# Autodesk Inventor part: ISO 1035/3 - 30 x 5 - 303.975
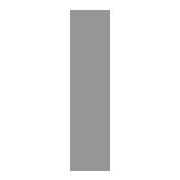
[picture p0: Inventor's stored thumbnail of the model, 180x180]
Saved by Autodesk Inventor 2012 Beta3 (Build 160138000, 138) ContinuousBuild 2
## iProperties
_CCFamilyMember: 18
_CCFamilyDisplayName: ISO 1035/3 - 1980 - Hot-rolled steel bars - Part 3: flat bars
_FrameMemberDoc: Frame Member File
_Version: 15.0.0
_GetPNFromCC: 1
Created: 2010-11
Part Number: ISO 1035/3 - 30 x 5 - 303.975
Material: Steel, Mild
Description: Hot-rolled steel bars - Part 3: flat bars
Document SubType Name: Modeling
Standard: ISO
Designer: Beta-8540w
Standard Revision: First edition 1980-11-01
Standards Organization: ISO
Language: en-US
Size Designation: 30x 5
Categories: <MemberInstance><Categories><Category DisplayName="Structural Shapes" InternalName="089c4875-fa83-4c05-b084-43b9cc11f5ed" Mnemonic="GRDR"><CategoryParameter Dis
Stock Number: 30x 5
Density: 7.86 g/cm^3
IsCustomPart: 1
G_L: 303.975 mm
G_W: 5.000 mm
G_H: 30.000 mm
Author: Beta-8540w
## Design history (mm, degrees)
node "Start plane"
node "End plane"
node "Driven Length"
  sketch "Sketch3"
    geometry: L1 (0, 0)-(10, 0) reference
    constraints: 2 end point, 1 horizontal
  workplane "Work Plane3"
  sketch "Sketch4"
    geometry: L1 (-2, 0)-(12, 0) reference; L2 (-2, 303.975)-(12, 303.975) reference
    dimensions: "d9" = 303.9749 distance between parallel lines of L1 L2 (derived)
sketch "Sweep Path"
  geometry: L1 through (40, 30) direction (1, 0); L2 through (-20, 135) direction (1, -0); L3 through (-20, 165) direction (1, 0); L4 through (40, 270) direction (1, 0); 14 other entities
  constraints: 20 horizontal
node "Orientation Work Plane"
feature "Body" dims "d10" = 0
body "Solid1"
sketch "Sketch"
  geometry: L1 (2.5, -15)-(-2.5, -15); L2 (-2.5, -15)-(-2.5, 15); L3 (-2.5, 15)-(2.5, 15); L4 (2.5, 15)-(2.5, -15); L5 (-6, 0)-(8, 0); L6 (0, -30)-(0, 40); L7 (0, 54)-(0, -44); L8 (-9.2, 0)-(13.2, 0)
  constraints: 16 end point, 2 collinear, 2 parallel, 1 horizontal, 1 perpendicular
  dimensions: "d0" = 30 distance between parallel lines of L3 L1 (= G_W); "d1" = 5 distance between parallel lines of L4 L2 (= G_H); "d4" = 2.5 distance between parallel lines of L6 L4 (= 0.5 x d1); "d5" = 15 distance between parallel lines of L5 L3 (= 0.5 x d0)
other parameters: "G_W" = 30 [user parameter; used in 1 equation term], "G_H" = 5 [user parameter; used in 1 equation term], "G_L" = 303.9749 (= d9) [user parameter], "G_OFFSET_START" = 0 [user parameter; used in 1 equation term], "G_OFFSET_END" = 0 [user parameter; used in 1 equation term], "d6" = 0 (computed from G_OFFSET_START), "d7" = 303.9749 (= G_OFFSET_END + B_L), "B_L" = 303.9749 [user parameter; used in 1 equation term], "d8" = 90 deg
